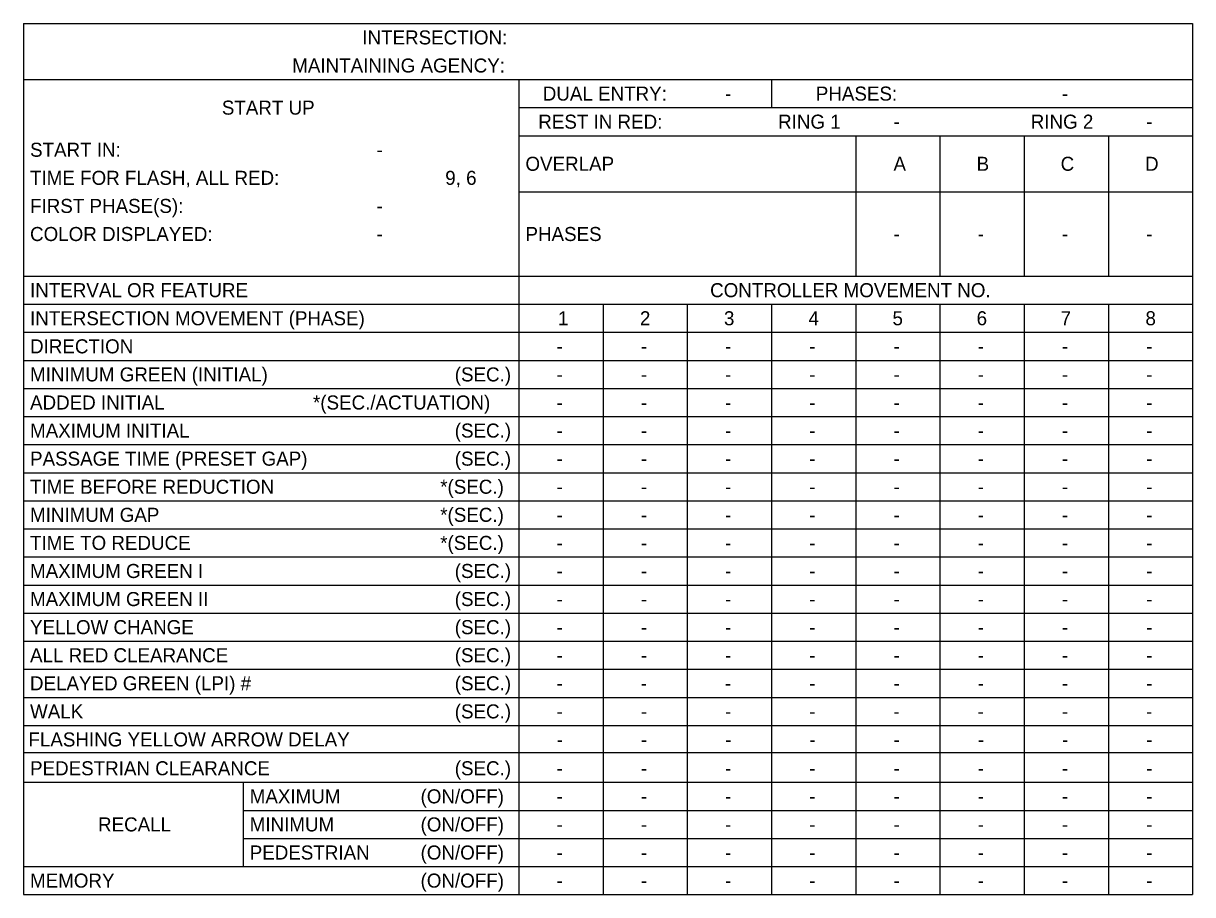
# Model space of a CAD drawing. Extents: x 22.8 to 118.4, y -49.9 to 44.8.
# Drawn here: x 44.62 to 56.29, y -49.91 to -41.23 of the extents above; entities that cross this region are included whole.
import ezdxf

# ---------------------------------------------------------------- set-up
doc = ezdxf.new("R2010")
doc.units = 0
doc.layers.add('SH_Text', color=7, linetype='Continuous')
doc.layers.add('ST_Text', color=7, linetype='Continuous')

msp = doc.modelspace()

# ---------------------------------------------------------------- linework, layer by layer
at = {"layer": 'SH_Text'}
for p, q in [((49.565, -49.633), (49.565, -49.913)), ((50.405, -49.633), (50.405, -49.913)), ((51.245, -49.633), (51.245, -49.913)), ((52.085, -49.633), (52.085, -49.913)), ((52.925, -49.633), (52.925, -49.913)), ((53.765, -49.633), (53.765, -49.913)), ((54.605, -49.633), (54.605, -49.913)), ((55.445, -49.633), (55.445, -49.913))]:
    msp.add_line(p, q, dxfattribs=at)
at = {"layer": 'ST_Text'}
for p, q in [((44.624, -41.226), (56.285, -41.226)), ((44.624, -41.226), (44.624, -49.913)), ((56.285, -41.226), (56.285, -49.913)), ((44.624, -41.786), (56.285, -41.786)), ((49.565, -41.786), (49.565, -49.633)), ((52.085, -41.786), (52.085, -42.066)), ((49.565, -42.066), (56.285, -42.066)), ((49.565, -42.346), (56.285, -42.346)), ((52.925, -42.346), (52.925, -43.746)), ((53.765, -42.346), (53.765, -43.746)), ((54.605, -42.346), (54.605, -43.746)), ((55.445, -42.346), (55.445, -43.746)), ((49.565, -42.906), (56.285, -42.906)), ((44.624, -43.746), (56.285, -43.746)), ((44.624, -44.026), (56.285, -44.026)), ((50.405, -44.026), (50.405, -49.633)), ((51.245, -44.026), (51.245, -49.633)), ((52.085, -44.026), (52.085, -49.633)), ((52.925, -44.026), (52.925, -49.633)), ((53.765, -44.026), (53.765, -49.633)), ((54.605, -44.026), (54.605, -49.633)), ((55.445, -44.026), (55.445, -49.633)), ((44.624, -44.306), (56.285, -44.306)), ((44.624, -44.586), (56.285, -44.586)), ((44.624, -44.866), (56.285, -44.866)), ((44.624, -45.146), (56.285, -45.146)), ((44.624, -45.426), (56.285, -45.426)), ((44.624, -45.706), (56.285, -45.706)), ((44.624, -45.986), (56.285, -45.986)), ((44.624, -46.266), (56.285, -46.266)), ((44.624, -46.546), (56.285, -46.546)), ((44.624, -46.826), (56.285, -46.826)), ((44.624, -47.106), (56.285, -47.106)), ((44.624, -47.386), (56.285, -47.386)), ((44.624, -47.666), (56.285, -47.666)), ((44.624, -47.946), (56.285, -47.946)), ((44.624, -47.946), (56.285, -47.946)), ((44.624, -48.226), (56.285, -48.226)), ((44.624, -48.495), (56.285, -48.495)), ((44.624, -48.793), (56.285, -48.793)), ((46.815, -48.793), (46.815, -49.633)), ((46.815, -49.073), (56.285, -49.073)), ((46.815, -49.353), (56.285, -49.353)), ((44.624, -49.633), (56.285, -49.633)), ((44.624, -49.913), (56.285, -49.913))]:
    msp.add_line(p, q, dxfattribs=at)

# ---------------------------------------------------------------- texts
for s, p in [('INTERSECTION:', (48.004, -41.436)), ('MAINTAINING AGENCY:', (47.305, -41.716)), ('DUAL ENTRY: ', (49.804, -41.996)), ('PHASES:', (52.527, -41.996)), ('-', (51.622, -41.996)), ('-', (54.982, -41.996)), ('START UP', (46.603, -42.136)), ('REST IN RED: ', (49.759, -42.276)), ('RING 1', (52.151, -42.276)), ('-', (53.302, -42.276)), ('RING 2', (54.671, -42.276)), ('-', (55.822, -42.276)), ('START IN: ', (44.69, -42.556)), ('-', (48.147, -42.556)), ('OVERLAP', (49.631, -42.696)), ('A', (53.302, -42.696)), ('B', (54.131, -42.696)), ('C', (54.969, -42.696)), ('D', (55.811, -42.696)), ('TIME FOR FLASH, ALL RED:   ', (44.69, -42.836)), ('9, 6', (48.831, -42.836)), ('FIRST PHASE(S):', (44.69, -43.116)), ('-', (48.147, -43.116)), ('COLOR DISPLAYED:', (44.69, -43.396)), ('PHASES', (49.631, -43.396)), ('-', (48.147, -43.396)), ('-', (53.302, -43.396)), ('-', (54.142, -43.396)), ('-', (54.982, -43.396)), ('-', (55.822, -43.396)), ('INTERVAL OR FEATURE', (44.69, -43.956)), ('CONTROLLER MOVEMENT NO.', (51.473, -43.956)), ('INTERSECTION MOVEMENT (PHASE)', (44.69, -44.236)), ('1', (49.956, -44.236)), ('2', (50.773, -44.236)), ('3', (51.611, -44.236)), ('4', (52.454, -44.236)), ('5', (53.292, -44.236)), ('6', (54.131, -44.236)), ('7', (54.969, -44.236)), ('8', (55.815, -44.236)), ('DIRECTION', (44.69, -44.516)), ('-', (49.942, -44.516)), ('-', (50.782, -44.516)), ('-', (51.622, -44.516)), ('-', (52.462, -44.516)), ('-', (53.302, -44.516)), ('-', (54.142, -44.516)), ('-', (54.982, -44.516)), ('-', (55.822, -44.516)), ('MINIMUM GREEN (INITIAL) ', (44.69, -44.796)), ('(SEC.)', (48.926, -44.796)), ('-', (49.942, -44.796)), ('-', (50.782, -44.796)), ('-', (51.622, -44.796)), ('-', (52.462, -44.796)), ('-', (53.302, -44.796)), ('-', (54.142, -44.796)), ('-', (54.982, -44.796)), ('-', (55.822, -44.796)), ('ADDED INITIAL', (44.69, -45.076)), ('*(SEC./ACTUATION)', (47.512, -45.076)), ('-', (49.942, -45.076)), ('-', (50.782, -45.076)), ('-', (51.622, -45.076)), ('-', (52.462, -45.076)), ('-', (53.302, -45.076)), ('-', (54.142, -45.076)), ('-', (54.982, -45.076)), ('-', (55.822, -45.076)), ('MAXIMUM INITIAL', (44.69, -45.356)), ('(SEC.)', (48.926, -45.356)), ('-', (49.942, -45.356)), ('-', (50.782, -45.356)), ('-', (51.622, -45.356)), ('-', (52.462, -45.356)), ('-', (53.302, -45.356)), ('-', (54.142, -45.356)), ('-', (54.982, -45.356)), ('-', (55.822, -45.356)), ('PASSAGE TIME (PRESET GAP)', (44.69, -45.636)), ('(SEC.)', (48.926, -45.636)), ('-', (49.942, -45.636)), ('-', (50.782, -45.636)), ('-', (51.622, -45.636)), ('-', (52.462, -45.636)), ('-', (53.302, -45.636)), ('-', (54.142, -45.636)), ('-', (54.982, -45.636)), ('-', (55.822, -45.636)), ('TIME BEFORE REDUCTION', (44.69, -45.916)), ('*(SEC.)', (48.781, -45.916)), ('-', (49.942, -45.916)), ('-', (50.782, -45.916)), ('-', (51.622, -45.916)), ('-', (52.462, -45.916)), ('-', (53.302, -45.916)), ('-', (54.142, -45.916)), ('-', (54.982, -45.916)), ('-', (55.822, -45.916)), ('MINIMUM GAP', (44.69, -46.196)), ('*(SEC.)', (48.781, -46.196)), ('-', (49.942, -46.196)), ('-', (50.782, -46.196)), ('-', (51.622, -46.196)), ('-', (52.462, -46.196)), ('-', (53.302, -46.196)), ('-', (54.142, -46.196)), ('-', (54.982, -46.196)), ('-', (55.822, -46.196)), ('TIME TO REDUCE', (44.69, -46.476)), ('*(SEC.)', (48.781, -46.476)), ('-', (49.942, -46.476)), ('-', (50.782, -46.476)), ('-', (51.622, -46.476)), ('-', (52.462, -46.476)), ('-', (53.302, -46.476)), ('-', (54.142, -46.476)), ('-', (54.982, -46.476)), ('-', (55.822, -46.476)), ('MAXIMUM GREEN I', (44.69, -46.756)), ('(SEC.)', (48.926, -46.756)), ('-', (49.942, -46.756)), ('-', (50.782, -46.756)), ('-', (51.622, -46.756)), ('-', (52.462, -46.756)), ('-', (53.302, -46.756)), ('-', (54.142, -46.756)), ('-', (54.982, -46.756)), ('-', (55.822, -46.756)), ('MAXIMUM GREEN II', (44.69, -47.036)), ('(SEC.)', (48.926, -47.036)), ('-', (49.942, -47.036)), ('-', (50.782, -47.036)), ('-', (51.622, -47.036)), ('-', (52.462, -47.036)), ('-', (53.302, -47.036)), ('-', (54.142, -47.036)), ('-', (54.982, -47.036)), ('-', (55.822, -47.036)), ('YELLOW CHANGE', (44.69, -47.316)), ('(SEC.)', (48.926, -47.316)), ('-', (49.942, -47.316)), ('-', (50.782, -47.316)), ('-', (51.622, -47.316)), ('-', (52.462, -47.316)), ('-', (53.302, -47.316)), ('-', (54.142, -47.316)), ('-', (54.982, -47.316)), ('-', (55.822, -47.316)), ('ALL RED CLEARANCE', (44.69, -47.596)), ('(SEC.)', (48.926, -47.596)), ('-', (49.942, -47.596)), ('-', (50.782, -47.596)), ('-', (51.622, -47.596)), ('-', (52.462, -47.596)), ('-', (53.302, -47.596)), ('-', (54.142, -47.596)), ('-', (54.982, -47.596)), ('-', (55.822, -47.596)), ('DELAYED GREEN (LPI) #', (44.689, -47.876)), ('(SEC.)', (48.926, -47.876)), ('-', (49.942, -47.876)), ('-', (50.781, -47.876)), ('-', (51.621, -47.876)), ('-', (52.461, -47.876)), ('-', (53.302, -47.876)), ('-', (54.142, -47.876)), ('-', (54.981, -47.876)), ('-', (55.822, -47.876)), ('WALK', (44.69, -48.156)), ('(SEC.)', (48.926, -48.156)), ('-', (49.941, -48.156)), ('-', (50.782, -48.156)), ('-', (51.622, -48.156)), ('-', (52.462, -48.156)), ('-', (53.301, -48.156)), ('-', (54.141, -48.156)), ('-', (54.982, -48.156)), ('-', (55.821, -48.156)), ('FLASHING YELLOW ARROW DELAY ', (44.674, -48.436)), ('-', (49.943, -48.436)), ('-', (50.783, -48.436)), ('-', (51.623, -48.436)), ('-', (52.463, -48.436)), ('-', (53.303, -48.436)), ('-', (54.143, -48.436)), ('-', (54.983, -48.436)), ('-', (55.823, -48.436)), ('PEDESTRIAN CLEARANCE', (44.69, -48.723)), ('(SEC.)', (48.926, -48.723)), ('-', (49.942, -48.723)), ('-', (50.782, -48.723)), ('-', (51.622, -48.723)), ('-', (52.462, -48.723)), ('-', (53.302, -48.723)), ('-', (54.142, -48.723)), ('-', (54.982, -48.723)), ('-', (55.822, -48.723)), ('MAXIMUM', (46.881, -49.003)), ('(ON/OFF)', (48.585, -49.003)), ('-', (49.942, -49.003)), ('-', (50.782, -49.003)), ('-', (51.622, -49.003)), ('-', (52.462, -49.003)), ('-', (53.302, -49.003)), ('-', (54.142, -49.003)), ('-', (54.982, -49.003)), ('-', (55.822, -49.003)), ('RECALL', (45.368, -49.283)), ('MINIMUM', (46.881, -49.283)), ('(ON/OFF)', (48.585, -49.283)), ('-', (49.942, -49.283)), ('-', (50.782, -49.283)), ('-', (51.622, -49.283)), ('-', (52.462, -49.283)), ('-', (53.302, -49.283)), ('-', (54.142, -49.283)), ('-', (54.982, -49.283)), ('-', (55.822, -49.283)), ('PEDESTRIAN', (46.881, -49.563)), ('(ON/OFF)', (48.585, -49.563)), ('-', (49.942, -49.563)), ('-', (50.782, -49.563)), ('-', (51.622, -49.563)), ('-', (52.462, -49.563)), ('-', (53.302, -49.563)), ('-', (54.142, -49.563)), ('-', (54.982, -49.563)), ('-', (55.822, -49.563)), ('MEMORY    ', (44.69, -49.843)), ('(ON/OFF)', (48.585, -49.843)), ('-', (49.942, -49.843)), ('-', (50.782, -49.843)), ('-', (51.622, -49.843)), ('-', (52.462, -49.843)), ('-', (53.302, -49.843)), ('-', (54.142, -49.843)), ('-', (54.982, -49.843)), ('-', (55.822, -49.843))]:
    msp.add_text(s, height=0.14, dxfattribs=at).set_placement(p)

doc.saveas('drawing.dxf')
